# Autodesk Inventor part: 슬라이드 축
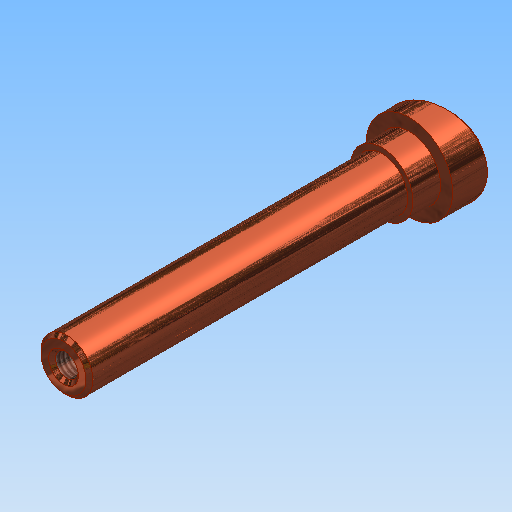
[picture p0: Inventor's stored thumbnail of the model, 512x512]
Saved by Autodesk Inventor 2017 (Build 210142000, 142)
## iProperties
Created: 2021-07
Part Number: 슬라이드 축
Document SubType Name: 모델링
Designer: mdu
Mass: 21.5729 g
Surface Area: 67.5859 cm^2
Volume: 21.5729 cm^3
Density: 1 g/cm^3
Material: 일반
Appearance: 금속 1400F 열
변환 표준: STEP AP214IS
파일 이름: C:\Users\SeoGD\Desktop\?쒗뿕\異?stp
전처리기: Build: 253, Release: 2010 SP1 - Date: Wed 07/29/2009
전송 단위: 밀리미터
불확실성: 0.01
Author: mdu
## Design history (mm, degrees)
sketch "스케치1"
  geometry: L1 (0, 100)-(7.5, 100); L2 (7.5, 100)-(7.5, 0); L3 (7.5, 0)-(12.5, 0); L4 (12.5, 0)-(12.5, -17); L5 (12.5, -17)-(0, -17); L6 (0, -17)-(0, 100); 1 further point
  constraints: 12 end point, 2 parallel, 2 point on line, 1 perpendicular, 1 vertical
  dimensions: "d0" = 100 distance from line of L1 point (0, 0); "d1" = 15 diameter of L2 L6; "d2" = 25 diameter of L4 L6; "d3" = 17 distance of L3.end L4.end
revolve "회전1" sketch "스케치1" stored, may be unused: angle "d4" = 90 deg
sketch "스케치2"
  geometry: L1 (12.5, 0)-(12.5, -17) reference; L2 (-12.5, -17)-(12.5, -17) reference; L3 (-12.5, 0)-(-12.5, -17) reference; L4 (12.5, -5)-(-12.5, -11.699); L5 (-12.5, 0)-(12.5, 0) reference; 1 further point
  constraints: 2 end point, 2 point on line
  dimensions: "d5" = 75 deg angle of L1 L4; "d6" = 5 distance from line of L4.start L5
extrude "돌출1" cut sketch "스케치2" stored distance "d7" = 10; taper "d8" = 0 deg
chamfer "모따기1" distance "d9" = 1; stored, may be unused: second distance "d10" = 2, angle "d11" = 45 deg
fillet "모깎기1" dims "d12" = 0.5
hole "구멍1" diameter "d15" = 6.647; stored, may be unused: countersink angle "d19" = 90 deg, drill point angle "d21" = 118 deg; dims "d13" = 10, "d14" = 10, "d16" = 17, "d17" = 4, "d18" = 2, "d20" = 20
chamfer "모따기2" distance "d22" = 1; stored, may be unused: second distance "d23" = 2, angle "d24" = 45 deg
sketch "스케치3"
  geometry: C1 r 9 at (0, 0); 1 further point
  constraints: 1 centre point, 1 coincident
  dimensions: "d25" = 18 diameter of C1
extrude "돌출2" join sketch "스케치3" distance "d26" = 8; taper "d27" = 0 deg
node "솔리드1"
node "솔리드 본체"
node "곡면 본체"
node "솔리드2"
